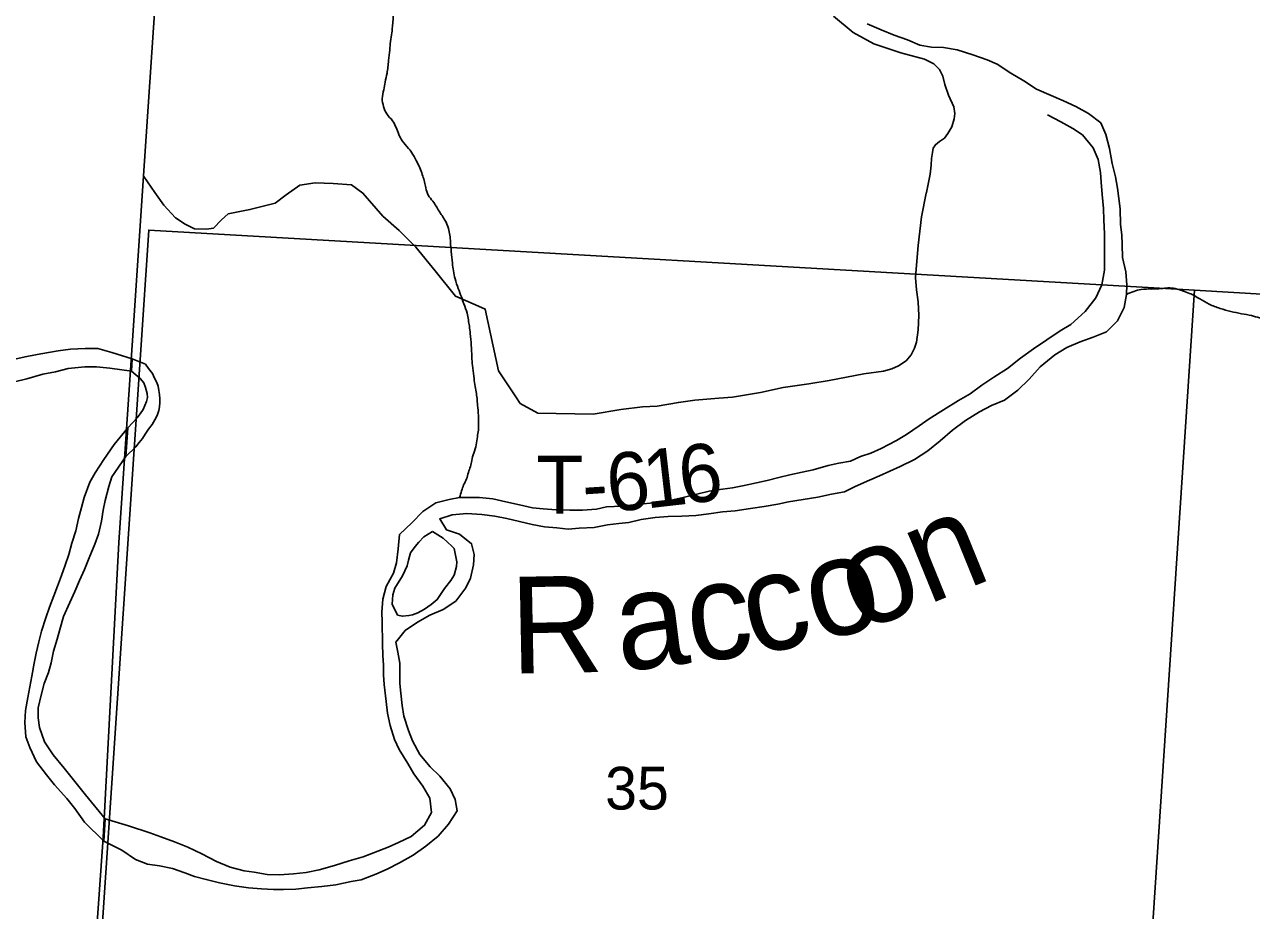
# Model space of a CAD drawing. Extents: x -13.7 to 34, y 0 to 32.3.
# Drawn here: x 25.84 to 27.041, y 19.456 to 20.324 of the extents above; entities that cross this region are included whole.
import ezdxf

# ---------------------------------------------------------------- set-up
doc = ezdxf.new("R2010")
doc.units = 0
for name, color, linetype in [('GM_X_Corporation', 7, 'Continuous'), ('GM_X_Major_River', 7, 'Continuous'), ('GM_X_Major_River_Text', 7, 'Continuous'), ('GM_X_Minor_River', 7, 'Continuous'), ('GM_X_Section_Text', 7, 'Continuous'), ('GM_X_Township_Road', 7, 'Continuous'), ('GM_X_Township_Road_Text', 7, 'Continuous')]:
    doc.layers.add(name, color=color, linetype=linetype)

msp = doc.modelspace()

# ---------------------------------------------------------------- linework, layer by layer
at = {"layer": 'GM_X_Corporation'}
for points in [[(25.8396, 18.3951), (25.8512, 18.5523), (25.8521, 18.5644), (25.8715, 18.8281), (25.8969, 19.1723), (25.8969, 19.2407), (25.917, 19.5276), (25.9325, 19.8164), (25.9462, 20.0191), (25.9566, 20.1753), (25.9834, 20.5724), (26.0026, 20.9), (23.5167, 20.9)], [(25.8396, 18.3951), (25.8512, 18.5523), (25.8521, 18.5644), (25.8715, 18.8281), (25.8969, 19.1723), (25.8969, 19.2407), (25.917, 19.5276), (25.9325, 19.8164), (25.9462, 20.0191), (25.9566, 20.1753), (25.9834, 20.5724), (26.0026, 20.9), (23.5167, 20.9)], [(29.9598, 20.9), (26.0026, 20.9), (25.9834, 20.5724), (25.9566, 20.1753), (25.9462, 20.0191), (25.9325, 19.8164), (25.917, 19.5276), (25.8969, 19.2407), (25.8969, 19.1723), (25.8715, 18.8281), (25.8521, 18.5644), (25.8512, 18.5523), (25.8396, 18.3951), (25.8286, 18.2247), (25.8036, 17.8534), (25.7648, 17.1991), (25.7595, 17.1252), (25.7591, 17.1039), (25.7561, 17.0683), (25.752, 17.037), (25.7481, 16.9763), (25.7164, 16.6052), (25.6857, 16.1459), (25.6733, 15.948)], [(29.9598, 20.9), (26.0026, 20.9), (25.9834, 20.5724), (25.9566, 20.1753), (25.9462, 20.0191), (25.9325, 19.8164), (25.917, 19.5276), (25.8969, 19.2407), (25.8969, 19.1723), (25.8715, 18.8281), (25.8521, 18.5644), (25.8512, 18.5523), (25.8396, 18.3951), (25.8286, 18.2247), (25.8036, 17.8534), (25.7648, 17.1991), (25.7595, 17.1252), (25.7591, 17.1039), (25.7561, 17.0683), (25.752, 17.037), (25.7481, 16.9763), (25.7164, 16.6052), (25.6857, 16.1459), (25.6733, 15.948)]]:
    msp.add_lwpolyline(points, dxfattribs=at)
for points in [[(26.9853, 20.0635), (26.9188, 19.0522), (25.8944, 19.1175), (25.9617, 20.1223)], [(28.0076, 20.0028), (27.9343, 18.9903), (27.9295, 18.9907), (26.9188, 19.0522), (26.9853, 20.0635)]]:
    msp.add_lwpolyline(points, close=True, dxfattribs=at)
at = {"layer": 'GM_X_Major_River'}
for p, q in [((25.9456, 19.9961), (25.9448, 19.9843)), ((25.9411, 19.9288), (25.9392, 19.9006)), ((25.9189, 19.5457), (25.9177, 19.5239))]:
    msp.add_line(p, q, dxfattribs=at)
for points in [[(26.8934, 20.2272), (26.8816, 20.2366), (26.8691, 20.2434), (26.857, 20.249), (26.8305, 20.2603), (26.8183, 20.2683), (26.8054, 20.2758), (26.7922, 20.2849), (26.7823, 20.289), (26.7683, 20.2939), (26.7528, 20.2988), (26.7395, 20.301), (26.7278, 20.3014), (26.7164, 20.3032), (26.7043, 20.3085), (26.6914, 20.313), (26.6785, 20.3183), (26.6649, 20.3243)], [(26.8415, 20.235), (26.8544, 20.2282), (26.8661, 20.2218), (26.8756, 20.2157), (26.8862, 20.2029), (26.8908, 20.1915), (26.8931, 20.1786), (26.8939, 20.1692), (26.895, 20.157), (26.8962, 20.1434), (26.8966, 20.1324), (26.897, 20.1187), (26.8971, 20.0831), (26.8945, 20.0687), (26.8888, 20.0558), (26.8782, 20.0425), (26.8643, 20.0299), (26.8537, 20.0235), (26.8276, 20.006), (26.8148, 19.9968), (26.8023, 19.9869), (26.7887, 19.9782), (26.777, 19.9706), (26.7656, 19.9618), (26.7543, 19.9553), (26.7395, 19.9462), (26.7255, 19.9374), (26.7157, 19.9306), (26.7032, 19.9222), (26.6934, 19.9161), (26.6787, 19.9085), (26.6685, 19.9039), (26.6582, 19.9005), (26.6484, 19.8959), (26.6371, 19.894), (26.6268, 19.8917), (26.6121, 19.8874), (26.6011, 19.8851), (26.589, 19.8825), (26.5784, 19.8801), (26.5671, 19.8771), (26.5565, 19.8748), (26.5444, 19.8721), (26.533, 19.8698), (26.5232, 19.8686), (26.5103, 19.8667), (26.4993, 19.864), (26.4834, 19.8602), (26.4729, 19.8579), (26.463, 19.8563), (26.4524, 19.8548), (26.4388, 19.8536), (26.4248, 19.852), (26.4097, 19.8512), (26.3998, 19.8489), (26.3862, 19.8481), (26.3737, 19.8481), (26.3604, 19.8484), (26.3476, 19.8492), (26.3374, 19.8503), (26.3245, 19.8533), (26.3112, 19.8563), (26.2983, 19.8593), (26.2855, 19.8604), (26.2658, 19.8603), (26.2556, 19.8584), (26.2427, 19.8553), (26.2299, 19.8469), (26.2193, 19.8355), (26.2072, 19.8241), (26.2057, 19.8101), (26.2042, 19.7964), (26.2012, 19.7862), (26.1941, 19.7733), (26.1907, 19.7608), (26.1899, 19.7482), (26.1903, 19.7388), (26.1904, 19.7172), (26.1908, 19.7058), (26.1916, 19.6963), (26.1916, 19.6868), (26.192, 19.6774), (26.1939, 19.6607), (26.1955, 19.6493), (26.1981, 19.6372), (26.2023, 19.6236), (26.2069, 19.6137), (26.2153, 19.6001), (26.221, 19.5899), (26.2301, 19.5778), (26.2369, 19.566), (26.2384, 19.552), (26.2317, 19.5395), (26.2184, 19.5284), (26.206, 19.5227), (26.1961, 19.5181), (26.1715, 19.5086), (26.1579, 19.5048), (26.1435, 19.5002), (26.1284, 19.496), (26.1159, 19.4933)], [(26.1841, 19.4916), (26.195, 19.4965), (26.2071, 19.5026), (26.2204, 19.5103), (26.2328, 19.519), (26.2449, 19.5289), (26.2551, 19.5407), (26.2634, 19.5536), (26.2615, 19.5646), (26.2566, 19.5752), (26.2467, 19.5877), (26.2372, 19.5967), (26.227, 19.6088), (26.2197, 19.6221), (26.2159, 19.6323), (26.2114, 19.6463), (26.2098, 19.6569), (26.2083, 19.6687), (26.2075, 19.6782), (26.2075, 19.6983), (26.2056, 19.7089), (26.2036, 19.7187), (26.2127, 19.7301), (26.2248, 19.7385), (26.2369, 19.7453), (26.2497, 19.7507), (26.2622, 19.7591), (26.272, 19.772), (26.2766, 19.7815), (26.2796, 19.7944), (26.2803, 19.8046), (26.2776, 19.8152), (26.2659, 19.8247), (26.253, 19.8288), (26.2465, 19.8394), (26.2586, 19.8436), (26.273, 19.8448), (26.2878, 19.8437), (26.3003, 19.8422), (26.312, 19.84), (26.337, 19.834), (26.3491, 19.8317), (26.3612, 19.8306), (26.3722, 19.8295), (26.3828, 19.8303), (26.3976, 19.8311), (26.4108, 19.8338), (26.4218, 19.835), (26.4316, 19.8361), (26.4437, 19.8388), (26.4574, 19.8408), (26.4702, 19.8419), (26.4835, 19.8423), (26.4971, 19.8428), (26.51, 19.8443), (26.5232, 19.8463), (26.5357, 19.8474), (26.5508, 19.8497), (26.5641, 19.8517), (26.5773, 19.854), (26.5879, 19.8563), (26.6167, 19.8609), (26.6299, 19.8636), (26.6428, 19.8659), (26.653, 19.8713), (26.667, 19.8774), (26.6768, 19.8816), (26.6973, 19.8907), (26.7112, 19.8976), (26.7241, 19.906), (26.7362, 19.9159), (26.7483, 19.9265), (26.7611, 19.936), (26.7747, 19.9444), (26.7865, 19.9505), (26.7993, 19.9558), (26.8122, 19.9657), (26.8235, 19.9764), (26.8341, 19.9885), (26.8484, 20), (26.8602, 20.0072), (26.8734, 20.0129), (26.8859, 20.0175), (26.8991, 20.0228), (26.9097, 20.0335), (26.9165, 20.0464), (26.9187, 20.0593), (26.9191, 20.0688), (26.9179, 20.0813), (26.9149, 20.0953), (26.9144, 20.1082), (26.914, 20.1177), (26.9129, 20.1279), (26.9125, 20.1431), (26.9113, 20.1533), (26.9098, 20.1635), (26.9079, 20.1745), (26.9048, 20.1874), (26.9021, 20.2022), (26.8983, 20.2158), (26.8934, 20.2272)], [(25.9456, 19.9961), (25.9257, 20.0024), (25.9117, 20.0062), (25.8996, 20.0065), (25.8851, 20.0058), (25.873, 20.0039), (25.8635, 20.0024), (25.8525, 20.0005), (25.8407, 19.9982), (25.8278, 19.9952)], [(25.9392, 19.9006), (25.949, 19.9099), (25.9524, 19.9144), (25.9554, 19.9182), (25.9581, 19.9224), (25.9615, 19.9273), (25.965, 19.9318), (25.9676, 19.9364), (25.9699, 19.9409), (25.9715, 19.9455), (25.9722, 19.9493), (25.9726, 19.9534), (25.9726, 19.9572), (25.9723, 19.9614), (25.9715, 19.9652), (25.9708, 19.9694), (25.9697, 19.9732), (25.9674, 19.9774), (25.9655, 19.9819), (25.9614, 19.9869), (25.9584, 19.991), (25.9456, 19.9961)], [(25.8304, 19.9736), (25.8422, 19.9766), (25.8581, 19.9812), (25.8703, 19.9834), (25.8828, 19.9868), (25.8992, 19.9883), (25.9105, 19.9883), (25.9235, 19.9872), (25.9448, 19.9843)], [(25.9448, 19.9843), (25.9534, 19.977), (25.9568, 19.9728), (25.9586, 19.9683), (25.9601, 19.9622), (25.9605, 19.9584), (25.9594, 19.9546), (25.9578, 19.9505), (25.9563, 19.9467), (25.9532, 19.9425), (25.9502, 19.9383), (25.9411, 19.9288)], [(25.9411, 19.9288), (25.9279, 19.9124), (25.9177, 19.8976), (25.9093, 19.8847), (25.904, 19.8753), (25.8986, 19.8605), (25.896, 19.8506), (25.8929, 19.84), (25.8902, 19.8278), (25.8864, 19.8157), (25.8834, 19.8047), (25.88, 19.7941), (25.8762, 19.7842), (25.8723, 19.7736), (25.8689, 19.7641), (25.8647, 19.7531), (25.8609, 19.7425), (25.8567, 19.7296), (25.8541, 19.719), (25.8514, 19.708), (25.8495, 19.6981), (25.8472, 19.6856), (25.8453, 19.675), (25.8434, 19.6647), (25.8411, 19.6518), (25.8403, 19.6401), (25.8414, 19.626), (25.8452, 19.6158), (25.8517, 19.6017), (25.8615, 19.5888), (25.8695, 19.579), (25.8816, 19.5657), (25.8892, 19.5558), (25.8987, 19.5425), (25.9177, 19.5239)], [(25.9189, 19.5457), (25.8998, 19.5692), (25.879, 19.5953), (25.868, 19.6086), (25.8596, 19.6211), (25.8547, 19.6351), (25.8536, 19.6446), (25.8536, 19.6545), (25.8563, 19.667), (25.8593, 19.6784), (25.8635, 19.689), (25.8662, 19.6985), (25.8685, 19.7099), (25.8719, 19.7216), (25.8746, 19.7311), (25.8784, 19.744), (25.8845, 19.7577), (25.8894, 19.7683), (25.894, 19.7793), (25.8989, 19.7899), (25.9035, 19.8013), (25.9088, 19.8149), (25.9126, 19.8244), (25.9153, 19.8373), (25.9172, 19.8479), (25.9191, 19.8574), (25.9226, 19.8711), (25.9256, 19.8806), (25.9392, 19.9006)], [(26.2394, 19.8272), (26.231, 19.8219), (26.2261, 19.8166), (26.2224, 19.8124), (26.2178, 19.8063), (26.216, 19.7991), (26.2145, 19.7934), (26.2099, 19.7836), (26.2024, 19.7718), (26.2005, 19.765), (26.1998, 19.7559), (26.2051, 19.7453)], [(26.2051, 19.7453), (26.21, 19.7441), (26.2164, 19.7449), (26.2199, 19.7457), (26.2251, 19.7476), (26.2316, 19.751), (26.238, 19.7556), (26.244, 19.7605), (26.2512, 19.7715), (26.2573, 19.7791), (26.2607, 19.7845), (26.2629, 19.7928), (26.2633, 19.7974), (26.2606, 19.8106), (26.2583, 19.8129), (26.25, 19.8205), (26.2394, 19.8272)], [(25.9626, 19.5321), (25.942, 19.5389), (25.9189, 19.5457)], [(26.1159, 19.4933), (26.1034, 19.4921), (26.0898, 19.4909), (26.0777, 19.4913), (26.0648, 19.4935), (26.055, 19.495), (26.0413, 19.4984), (26.0281, 19.504), (26.0137, 19.5116), (26, 19.518), (25.9868, 19.5232), (25.9735, 19.5281), (25.9626, 19.5321)], [(25.9177, 19.5239), (25.9353, 19.5151)], [(25.9353, 19.5151), (25.9486, 19.5061), (25.9603, 19.5015), (25.9721, 19.4997), (25.9849, 19.4971), (25.9971, 19.4929), (26.0065, 19.4892), (26.0179, 19.4865), (26.0308, 19.4832), (26.0455, 19.4802), (26.0592, 19.4783), (26.0721, 19.4772), (26.0838, 19.4765), (26.0936, 19.4765), (26.1057, 19.4769), (26.1171, 19.4781), (26.1311, 19.4797), (26.1447, 19.4812), (26.1599, 19.4843), (26.1697, 19.4862), (26.1841, 19.4916)]]:
    msp.add_lwpolyline(points, dxfattribs=at)
at = {"layer": 'GM_X_Minor_River'}
for points in [[(26.2658, 19.8603), (26.2679, 19.867), (26.2699, 19.8727), (26.2728, 19.8786), (26.2745, 19.885), (26.2766, 19.8907), (26.2779, 19.8967), (26.2797, 19.9039), (26.2823, 19.9121), (26.2833, 19.9197), (26.2843, 19.9265), (26.2844, 19.9322), (26.2844, 19.9409), (26.2835, 19.9508), (26.283, 19.9573), (26.2821, 19.9638), (26.2808, 19.9711), (26.2799, 19.9791), (26.2784, 19.9897), (26.2779, 19.9981), (26.2764, 20.021), (26.2755, 20.0282), (26.2745, 20.0343), (26.2732, 20.0408), (26.2701, 20.05), (26.2677, 20.057), (26.2646, 20.065), (26.2615, 20.0746), (26.2598, 20.0823), (26.2589, 20.0899), (26.2578, 20.1013), (26.257, 20.1105), (26.2564, 20.1173), (26.2551, 20.1238), (26.2516, 20.1319), (26.2458, 20.1409), (26.2397, 20.1506), (26.2353, 20.1564), (26.2329, 20.1637), (26.2316, 20.1695), (26.2299, 20.1752), (26.2278, 20.1817), (26.2246, 20.1883), (26.2203, 20.1964), (26.216, 20.2023), (26.2098, 20.2097), (26.2037, 20.2228), (26.2002, 20.2294), (26.1947, 20.236), (26.1915, 20.2433), (26.1902, 20.251), (26.1917, 20.2597), (26.1931, 20.2672), (26.1949, 20.2759), (26.1958, 20.2819), (26.1964, 20.2884), (26.1975, 20.2986), (26.1982, 20.3069), (26.1996, 20.3156), (26.2002, 20.3213), (26.2008, 20.3281), (26.2006, 20.335), (26.1993, 20.3411), (26.1976, 20.348), (26.1956, 20.3556), (26.1936, 20.3629), (26.1913, 20.3729), (26.1888, 20.3802), (26.186, 20.3863), (26.1821, 20.3941), (26.1797, 20.4025), (26.1769, 20.4091), (26.1695, 20.4161), (26.1607, 20.4233), (26.1548, 20.4307), (26.149, 20.4389), (26.1455, 20.4469), (26.1427, 20.4554), (26.1389, 20.4646), (26.1372, 20.4715), (26.1347, 20.4773), (26.1312, 20.4843), (26.1287, 20.4908), (26.1294, 20.498), (26.1327, 20.5066), (26.1359, 20.513), (26.1392, 20.5209), (26.1409, 20.5269), (26.1419, 20.5329), (26.1417, 20.5398), (26.139, 20.5475), (26.1357, 20.5533), (26.1302, 20.5588), (26.1232, 20.5651), (26.1173, 20.5702), (26.111, 20.5735), (26.1039, 20.5779)], [(26.9187, 20.0593), (26.933, 20.0642), (26.9433, 20.0646), (26.9528, 20.065), (26.9592, 20.0656), (26.9664, 20.065), (26.9736, 20.0628), (26.9803, 20.0603), (26.9904, 20.055), (26.9997, 20.0498), (27.0102, 20.0456), (27.0313, 20.0404), (27.0411, 20.0385), (27.049, 20.0364), (27.0626, 20.0329), (27.0701, 20.0311), (27.0799, 20.0293), (27.0874, 20.0275), (27.0957, 20.025), (27.104, 20.0228), (27.1115, 20.0206), (27.1201, 20.0181), (27.1281, 20.0167), (27.1356, 20.0149), (27.1443, 20.0123), (27.1537, 20.0097), (27.1616, 20.008), (27.1691, 20.0066), (27.1752, 20.0056), (27.1854, 20.0041), (27.1941, 20.0031), (27.2058, 20.0023), (27.2126, 20.0021), (27.221, 20.003), (27.2279, 20.0039), (27.2336, 20.0048), (27.2397, 20.0065), (27.2458, 20.0078), (27.2523, 20.0091), (27.2588, 20.0101), (27.2665, 20.0117), (27.2738, 20.0141), (27.281, 20.0154), (27.2883, 20.0171), (27.2967, 20.0183), (27.305, 20.0188), (27.3141, 20.0185), (27.3221, 20.0178), (27.3308, 20.0172), (27.3411, 20.0172), (27.3509, 20.018), (27.3612, 20.0196), (27.3719, 20.0211), (27.3803, 20.0224), (27.3895, 20.024), (27.4021, 20.0266), (27.4078, 20.0275), (27.417, 20.0291), (27.4265, 20.03), (27.4349, 20.0308), (27.4425, 20.0302), (27.4512, 20.0295), (27.4599, 20.0285), (27.4659, 20.0279), (27.4727, 20.0269), (27.4784, 20.026), (27.4848, 20.0246), (27.492, 20.0232), (27.4995, 20.0215), (27.5074, 20.0197), (27.5153, 20.0171), (27.5213, 20.0154), (27.5277, 20.0129), (27.5344, 20.0097), (27.54, 20.0064), (27.5455, 20.0025), (27.5522, 19.9973), (27.5597, 19.9929), (27.5682, 19.9869), (27.5745, 19.9825), (27.5827, 19.9773), (27.5894, 19.9729), (27.5957, 19.9689), (27.6031, 19.9648), (27.6095, 19.9612), (27.6154, 19.958), (27.6226, 19.9551), (27.6289, 19.9526), (27.6387, 19.9496), (27.6466, 19.9478), (27.6557, 19.946), (27.6643, 19.9442), (27.6723, 19.9428), (27.6802, 19.9418), (27.6885, 19.9407), (27.6961, 19.9401)]]:
    msp.add_spline(points, degree=3, dxfattribs=at)
at = {"layer": 'GM_X_Township_Road'}
for points in [[(26.3209, 19.9589), (26.3252, 19.9525), (26.3425, 19.943), (26.3966, 19.942), (26.4239, 19.9466), (26.445, 19.9493), (26.4594, 19.95), (26.4801, 19.9535), (26.4962, 19.9558), (26.5197, 19.9576), (26.5329, 19.9588), (26.5603, 19.9634), (26.5827, 19.9683), (26.6076, 19.9719), (26.6276, 19.9751), (26.6615, 19.9814), (26.6809, 19.9842), (26.689, 19.9864), (26.6954, 19.9894), (26.7031, 19.9943), (26.7079, 20.0001), (26.7111, 20.0067), (26.713, 20.0127), (26.7146, 20.0247), (26.7153, 20.0388), (26.7146, 20.0519), (26.713, 20.0637), (26.7123, 20.0759), (26.7134, 20.092), (26.7148, 20.1073), (26.7181, 20.1352), (26.7227, 20.1585), (26.7229, 20.1592), (26.7264, 20.1769), (26.7275, 20.1857), (26.7279, 20.1923), (26.7287, 20.1983), (26.7296, 20.2025), (26.7316, 20.2059), (26.7356, 20.209), (26.7406, 20.2124), (26.7439, 20.217), (26.7476, 20.2235), (26.7499, 20.2311), (26.7506, 20.2364), (26.7496, 20.2429), (26.7444, 20.2544), (26.7407, 20.265), (26.739, 20.2731), (26.7356, 20.2795), (26.7301, 20.285), (26.7211, 20.2897), (26.6978, 20.2959), (26.6713, 20.3047), (26.6512, 20.3159), (26.632, 20.3318)], [(25.9569, 20.1748), (25.9675, 20.1592), (25.9764, 20.1466), (25.9878, 20.1343), (25.9973, 20.1282), (26.0066, 20.1234), (26.0183, 20.1232), (26.025, 20.1243), (26.0328, 20.1324), (26.0395, 20.1382), (26.0607, 20.1424), (26.0855, 20.1485), (26.0962, 20.1567), (26.1096, 20.1662), (26.1247, 20.1687), (26.1423, 20.1678), (26.1601, 20.1667), (26.1713, 20.1586), (26.1909, 20.136), (26.2068, 20.122), (26.2232, 20.1056), (26.242, 20.0824), (26.2618, 20.0575), (26.2816, 20.0492), (26.2911, 20.045), (26.304, 19.9844), (26.3209, 19.9589)]]:
    msp.add_lwpolyline(points, dxfattribs=at)

# ---------------------------------------------------------------- texts
at = {"layer": 'GM_X_Major_River_Text'}
for s, height, rotation, p in [('on', 0.09469, 22.0989, (26.6585, 19.7286)), ('co', 0.0947, 13.1008, (26.5531, 19.705)), ('R', 0.0947, 1.1029, (26.3162, 19.6879)), ('ac', 0.0947, 7.102, (26.4232, 19.6899))]:
    msp.add_text(s, height=height, rotation=rotation, dxfattribs=at).set_placement(p)
at = {"layer": 'GM_X_Section_Text'}
msp.add_text('35', height=0.04186, rotation=0, dxfattribs=at).set_placement((26.4084, 19.5549))
at = {"layer": 'GM_X_Township_Road_Text'}
for s, rotation, p in [('6', 6.8816, (26.4837, 19.8536)), ('T', 359.9957, (26.3409, 19.8446)), ('6', 5.1433, (26.4122, 19.8463)), ('1', 6.5284, (26.4486, 19.8496)), ('-', 3.7069, (26.3874, 19.8447))]:
    msp.add_text(s, height=0.0568, rotation=rotation, dxfattribs=at).set_placement(p)

doc.saveas('drawing.dxf')
